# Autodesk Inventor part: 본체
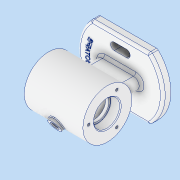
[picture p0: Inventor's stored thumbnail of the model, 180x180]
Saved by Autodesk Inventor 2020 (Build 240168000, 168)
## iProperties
Created: 2022-02
Part Number: 본체
Material: 알루미늄 6061
Document SubType Name: Modeling
Designer: 602-04
Density: 0.1 g/cm^3
Appearance: 알루미늄 - 평지
Mass: 18.3424 g
Surface Area: 489.733 cm^2
Volume: 183.424 cm^3
Author: 602-04
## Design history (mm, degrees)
sketch "스케치1"
  geometry: L1 (-35.496, 38)-(35.496, 38); L2 (-35.496, -38)-(35.496, -38); A1 r 52 centre (0, 0) between (-35.496, 38) and (-35.496, -38); A2 r 52 centre (0, 0) between (35.496, -38) and (35.496, 38); 1 further point
  constraints: 4 end point, 4 point on circle, 2 centre point, 2 horizontal, 1 coincident
  dimensions: "d1" = 38 distance from line of point (0, 0) L1; "d2" = 38 distance from line of L2 point (0, 0); "d3" = 52 radius of A2; "d4" = 52 radius of A1
extrude "돌출1" new body sketch "스케치1" distance "d5" = 10; taper "d6" = 0 deg
node "작업 평면1"
sketch "스케치2"
  geometry: L1 (-36, 0)-(36, 0); L2 (-36, 0)-(-36, 30); L3 (-36, 30)-(36, 30); L4 (36, 30)-(36, 0); L5 (-36, 16)-(-24, 16); L6 (-24, 16)-(-24, 14); L7 (-24, 14)-(-20, 14); L8 (-20, 14)-(-20, 25); L9 (-20, 25)-(20, 25); L10 (20, 25)-(20, 14); L11 (20, 14)-(24, 14); L12 (24, 14)-(24, 16); L13 (24, 16)-(36, 16); 2 further points
  constraints: 26 end point, 8 perpendicular, 4 point on line, 2 horizontal, 2 vertical, 1 coincident, 1 midpoint
  dimensions: "d8" = 72 distance of L1.start L1.end; "d9" = 60 diameter of L3 L1; "d10" = 50 diameter of L9 L1; "d11" = 32 diameter of L5 L1; "d12" = 28 diameter of L11 L1; "d13" = 32 diameter of L13 L1; "d14" = 12 distance between parallel lines of L6 L2; "d15" = 40 distance between parallel lines of L10 L8; "d16" = 12 distance between parallel lines of L4 L12; "d17" = 4 distance between parallel lines of L8 L6
revolve "회전1" sketch "스케치2" stored, may be unused: angle "d18" = 90 deg
sketch "스케치3"
  geometry: L1 (-19, 0)-(19, 0); L2 (-19, 7)-(19, 7); L3 (19, -7)-(-19, -7); A1 r 7 centre (-19, 0) between (-19, 7) and (-19, -7); A2 r 7 centre (19, 0) between (19, -7) and (19, 7); 2 further points
  constraints: 8 end point, 4 point on circle, 4 tangent, 2 centre point, 1 coincident, 1 horizontal, 1 midpoint, 1 parallel
  dimensions: "d19" = 14 distance between parallel lines of L3 L2; "d21" = 38 distance of L1.end L1.start
extrude "돌출2" join sketch "스케치3" stored distance "d22" = 10; taper "d23" = 0 deg
node "작업 평면2"
sketch "스케치4"
  geometry: L1 (0, 0)-(-28.579, -16.5); L2 (0, 0)-(-30, 0); 1 further point
  constraints: 4 end point, 1 horizontal, 1 horizontal alignment, 1 other
  dimensions: "d25" = 30 deg angle of L2 L1; "d26" = 33 distance of L1.start L1.end
node "작업 평면3"
sketch "스케치6"
  geometry: C1 r 8 at (0, 0); 1 further point
  constraints: 1 centre point
  dimensions: "d27" = 16 diameter of C1
extrude "돌출3" join sketch "스케치6" stored distance "d28" = 10; taper "d29" = 0 deg
sketch "스케치7"
  geometry: L1 (0, 0)-(-23, 0); L2 (0, 0)-(11.5, 19.919); L3 (0, 0)-(11.5, -19.919); A1 r 23 centre (0, 0) between (-23, 0) and (11.5, 19.919); 4 further points
  constraints: 6 end point, 3 coincident, 3 point on circle, 1 centre point, 1 horizontal
  dimensions: "d30" = 46 diameter of A1; "d31" = 120 deg angle of L2 L1; "d32" = 120 deg angle of L3 L1
hole "구멍1" sketch "스케치7" at (-23, 0), (11.5, 19.919), (11.5, -19.919) diameter "d33" = 3.242; stored, may be unused: countersink angle "d37" = 82 deg, drill point angle "d39" = 118 deg; dims "d34" = 8, "d35" = 3.023, "d36" = 2, "d38" = 10
sketch "스케치8"
  geometry: L1 (7.5, -24)-(-7.5, -24); L2 (7.5, -28.5)-(-7.5, -28.5); L3 (-7.5, -19.5)-(7.5, -19.5); L4 (7.5, 24)-(-7.5, 24); L5 (7.5, 28.5)-(-7.5, 28.5); L6 (-7.5, 19.5)-(7.5, 19.5); A1 r 4.5 centre (7.5, -24) between (7.5, -28.5) and (7.5, -19.5); A2 r 4.5 centre (-7.5, -24) between (-7.5, -19.5) and (-7.5, -28.5); A3 r 4.5 centre (7.5, 24) between (7.5, 19.5) and (7.5, 28.5); A4 r 4.5 centre (-7.5, 24) between (-7.5, 28.5) and (-7.5, 19.5); 3 further points
  constraints: 16 end point, 8 point on circle, 8 tangent, 4 centre point, 3 parallel, 2 midpoint, 2 vertical alignment, 1 horizontal
  dimensions: "d40" = 24 distance of point (0, 0) point (0, -24); "d41" = 24 distance of point (0, 24) point (0, 0); "d42" = 9 distance between parallel lines of L3 L2; "d43" = 9 distance between parallel lines of L5 L6; "d44" = 15 distance of L1.end L1.start; "d45" = 15 distance of L4.end L4.start
extrude "돌출4" cut sketch "스케치8" distance "d46" = 10; taper "d47" = 0 deg
sketch "스케치9"
  geometry: C1 r 8 at (0, 0) reference; 2 further points
  constraints: 1 coincident
hole "구멍2" sketch "스케치9" at (0, 0) diameter "d48" = 8; stored, may be unused: countersink angle "d52" = 82 deg, drill point angle "d54" = 118 deg; dims "d49" = 8, "d50" = 3.023, "d51" = 2, "d53" = 10
fillet "모깎기1" dims "d58" = 1
chamfer "모따기2" distance "d59" = 1; stored, may be unused: second distance "d60" = 2, angle "d61" = 45 deg
fillet "모깎기2" dims "d62" = 0.3, "d63" = 3
fillet "모깎기3" dims "d64" = 3
fillet "모깎기4" dims "d65" = 3
sketch "스케치10"
  geometry: C1 r 42.5 at (0, 0); 1 further point
  constraints: 1 centre point, 1 coincident, 1 other
  dimensions: "d66" = 85 diameter of C1
feature "엠보싱1" sketch "스케치10" dims "d1" = 38, "d2" = 38, "d3" = 52, "d4" = 52, "d8" = 72, "d9" = 60, "d10" = 50, "d11" = 32, "d12" = 28, "d13" = 32, "d14" = 12, "d15" = 40, "d16" = 12, "d17" = 4, "d67" = 0.5, "d68" = 0
fillet "모깎기5" dims "d69" = 1
node "솔리드1"
mirror "미러1"
feature "A9D066F2-1C7D-4E18-AEED-F7BC21143FA4" dims "d48" = 8, "d49" = 8, "d50" = 3.023, "d51" = 2, "d52" = 82 deg, "d53" = 10, "d54" = 118 deg
other parameters: "d0" = 52, "d7" = 62, "d24" = -36
